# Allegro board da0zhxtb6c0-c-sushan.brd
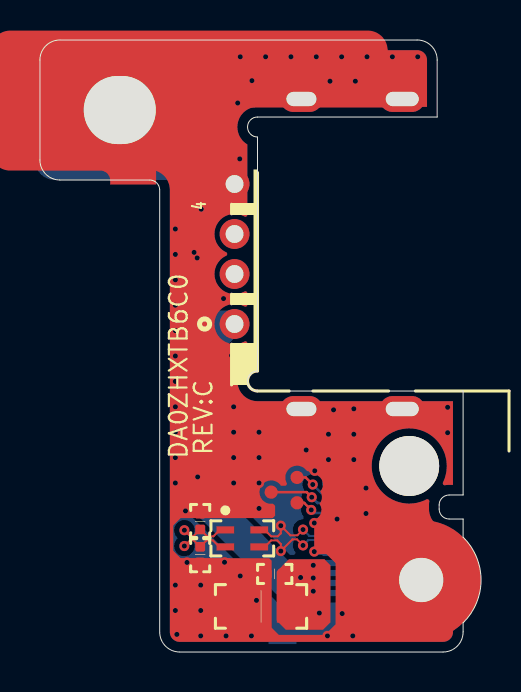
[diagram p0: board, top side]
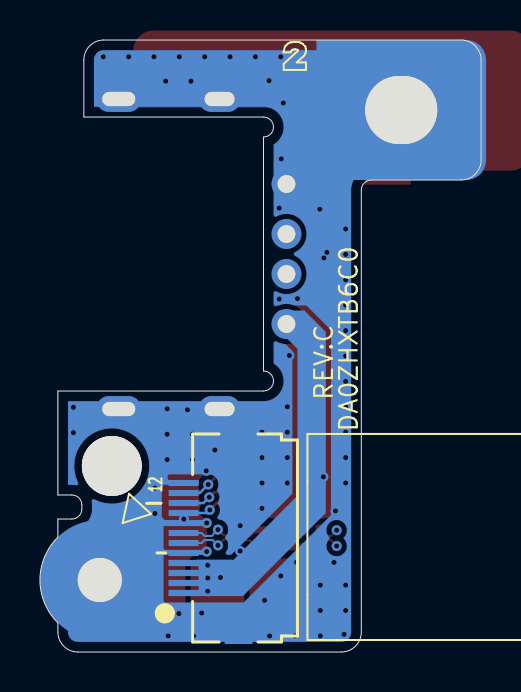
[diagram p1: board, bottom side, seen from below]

Outline 22.1 x 30.6 mm; copper layers: TOP, GND, IN1, IN2, VCC, BOTTOM. Coordinates in mm from the lower left corner of the outline.
Outline path: 0,29.6 0,24.6 arc(0.29,23.89) 1,23.6 5.5,23.6 arc(5.85,23.45) 6,23.1 6,1 arc(6.29,0.29) 7,0 20.2,0 arc(20.91,0.29) 21.2,1 21.2,1.46 arc(22.1,3.6) 21.2,5.74 21.2,6.65 20.5,6.65 arc(20.15,6.8) 20,7.15 20,7.35 arc(20.15,7.7) 20.5,7.85 21.2,7.85 21.2,13.05 10.9,13.05 arc(10.4,13.55) 10.9,14.05 10.9,25.75 arc(10.4,26.25) 10.9,26.75 19.9,26.75 19.9,29.6 arc(19.61,30.31) 18.9,30.6 1,30.6 arc(0.29,30.31) 0,29.6

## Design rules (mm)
constraint set DEFAULT: min track width 0.127

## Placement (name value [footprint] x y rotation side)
C1  100u/6.3v_1206  [C1206]  11.08 2.28 180 top
C2  0.1u/10v_4  [C0402]  11.76 3.9 0 top
CN1  ffc_conn  [AF712L-A2G1T-12P-L-SMT]  12.15 5.7 90 bottom
CN2  usb_con  [USB-C107V3-10406-L-4P-L]  18.15 19.9 90 top
D7  5v/30v/0.2p_4  [C0402]  8.03 6.52 270 top
D8  5v/30v/0.2p_4  [C0402]  8.03 4.87 90 top
HOLE1  *h-c118d118n  [H-C118D118N]  18.5 9.3 0 top
HOLE2  *h-c236d87p2  [H-C236D87P2]  19.1 3.6 0 top
HOLE3  *h-tc236bsdo142x134p2  [H-TC236BSDO142X134P2]  4 27.1 0 top
HOLE4  *spad-zhx-np  [SPAD-ZHX-NP]  7.47 27.22 0 top
L1  mcm2012b900gbe/400ma/90ohm  [CHOKE-DLW21S-4P]  10.14 5.68 0 top
NOREF  -  []  -27.94 -62.16 0 top
NOREF#2  -  []  22.86 -20 0 top
TP1  *pad  [TP2650]  12.88 7.46 0 top
TP2  *pad  [TP2650]  11.58 7.99 0 top
TP3  *pad  [TP2650]  12.88 8.73 0 top

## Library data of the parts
C1 = C1206
C2 D7 D8 = C0402
CN1 = AF712L-A2G1T-12P-L-SMT
CN2 = USB-C107V3-10406-L-4P-L
HOLE1 = H-C118D118N
HOLE2 = H-C236D87P2
HOLE3 = H-TC236BSDO142X134P2
HOLE4 = SPAD-ZHX-NP
L1 = CHOKE-DLW21S-4P
TP1-TP3 = TP2650

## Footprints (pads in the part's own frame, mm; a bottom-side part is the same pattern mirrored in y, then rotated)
AF712L-A2G1T-12P-L-SMT
  rect 0.305x1.499 smd: 1(-2.75,2.75) 2(-2.25,2.75) 3(-1.75,2.75) 4(-1.25,2.75) 5(-0.75,2.75) 6(-0.25,2.75) 7(0.25,2.75) 8(0.75,2.75) 9(1.25,2.75) 10(1.75,2.75) 11(2.25,2.75) 12(2.75,2.75)
  rect 1.803x1.397 smd: 13(-4.4,0) 14(4.4,0)
C0402
  custom 0.12x0.12 smd: 1(0.39,0) 2(-0.39,0)
C1206
  rect 1.219x1.626 smd: 1(1.4,0) 2(-1.4,0)
CHOKE-DLW21S-4P
  rect 0.889x0.356 smd: 1(-0.85,0.425) 2(0.85,0.425) 3(0.85,-0.425) 4(-0.85,-0.425)
H-C118D118N
  round 2.997 hole 2.997 unplated: (0,0)
H-C236D87P2
  round 5.994 hole 2.21: 1(0,0)
H-TC236BSDO142X134P2
  round 5.994 hole 3.607x3.404: 1(0,0)
SPAD-ZHX-NP
  custom 1.925x1.925 smd: 1(0,0)
TP2650
  round 0.66 smd: 1(0,0)
USB-C107V3-10406-L-4P-L
  round 1.499 hole 0.889: 1(-3.5,8.4) 2(-1,8.4) 3(1,8.4) 4(3.5,8.4)
  oval 1.295x2.108 hole 0.711x1.499: 5(-7.75,5.05) 6(7.75,5.05)
  oval 1.295x2.261 hole 0.711x1.651: 7(-7.75,0) 8(7.75,0)

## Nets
5VUSB_1: C1.2 C2.1 CN1.1 CN1.2 CN1.3 CN1.4 CN2.1
GND: C1.1 C2.2 CN1.5 CN1.8 CN1.12 CN1.13 CN1.14 CN2.4 CN2.5 CN2.6 CN2.7 CN2.8 D7.2 D8.2 HOLE2.1 HOLE3.1 HOLE4.1
NBSWON#: CN1.9 TP1.1
USBP1+: CN1.7 L1.2
USBP1+_CN: CN2.3 D7.1 L1.1
USBP1-: CN1.6 L1.3
USBP1-_CN: CN2.2 D8.1 L1.4
VOLUME_DOWN#: CN1.11 TP3.1
VOLUME_UP#: CN1.10 TP2.1

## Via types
v1: diameter 0.508, hole 0.254, TOP to BOTTOM, 85 vias

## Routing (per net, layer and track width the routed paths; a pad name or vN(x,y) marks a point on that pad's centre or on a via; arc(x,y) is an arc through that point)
5VUSB_1:
  vias: v1(13.06,3.73) v1(13.69,4.34) v1(13.69,3.7) v1(13.69,3.04) v1(14,1.95)
GND:
  vias: v1(6.78,21.15) v1(6.78,19.88) v1(6.78,18.61) v1(6.78,17.34) v1(6.78,16.07) v1(6.78,14.8) v1(6.78,13.53) v1(6.78,12.26) v1(6.78,10.99) v1(6.78,9.72) v1(6.78,8.45) v1(6.78,3.34) v1(6.78,2.07) v1(6.86,0.88) v1(7.29,7.05) v1(7.37,4.48) v1(7.72,19.98) v1(7.88,19.7) v1(7.9,8.75) v1(8.08,22.14) v1(8.05,3.34) v1(8.05,2.07) v1(8.05,0.8) v1(9.2,17.67) v1(9.25,4.49) v1(9.32,0.8) v1(9.6,14.83) v1(9.71,12.26) v1(9.71,10.99) v1(9.71,9.72) v1(9.71,8.45) v1(9.91,27.45) v1(10.04,29.76) v1(10.01,24.66) v1(10.04,3.8) v1(10.11,22.19) v1(10.11,17.64) v1(10.62,28.57) v1(10.59,0.8) v1(10.85,2.58) v1(10.98,10.99) v1(10.98,9.72) v1(10.98,8.45) v1(10.98,7.18) v1(11.31,29.76) v1(12.58,29.76) v1(13.34,10.1) v1(13.74,6.45) v1(13.74,5.02) v1(13.85,29.76) v1(13.77,9.06) v1(14.4,0.8) v1(14.53,28.54) v1(14.46,10.89) v1(14.46,9.62) v1(14.71,12.11) v1(14.89,6.65) v1(15.12,29.76) v1(15.14,1.92) v1(15.73,12.16) v1(15.73,10.89) v1(15.73,9.62) v1(15.67,0.8) v1(15.8,28.54) v1(16.33,8.2) v1(16.33,6.93) v1(16.39,29.76) v1(17.66,29.76) v1(18.93,29.76) v1(20.42,12.23) v1(20.42,10.96)
NBSWON#: length 2.2
  TOP w0.127: TP1.1 13.24,7.46 v1(13.59,7.1)
  BOTTOM w0.127: CN1.9 13.75,6.95 v1(13.59,7.1)
USBP1+: length 5
  TOP w0.102: v1(13.18,6.12) 12.89,5.83 12.55,5.83 v1(12.07,6.32) 12.07,5.94 11.92,5.78 11.58,5.78 11.26,6.11 L1.2
  BOTTOM w0.102: CN1.7 14,5.95 13.85,5.8 13.5,5.8 v1(13.18,6.12)
USBP1+_CN: length 20.5
  TOP w0.102: v1(7.24,6.09) 7.53,5.8 7.69,5.8 D7.1 8.38,5.78 8.69,5.78 9.01,6.11 L1.1
  IN1 w0.14: v1(7.24,6.09) 7.5,5.82 7.92,5.82 8.27,6.17 8.27,7.58 7.47,8.38 7.47,19.65 7.86,20.05 8.9,20.05 CN2.3
USBP1-: length 5
  TOP w0.102: L1.3 11.26,5.26 11.58,5.58 11.89,5.58 12.07,5.4 v1(12.07,5.05) 12.65,5.63 12.88,5.63 v1(13.18,5.33)
  BOTTOM w0.102: CN1.6 14,5.45 13.85,5.6 13.45,5.6 v1(13.18,5.33)
USBP1-_CN: length 20.5
  TOP w0.102: v1(7.24,5.3) 7.53,5.59 7.69,5.59 D8.1 8.35,5.58 8.66,5.58 8.99,5.26 L1.4
  IN1 w0.14: CN2.2 8.87,19.78 7.97,19.78 7.74,19.54 7.74,8.49 8.54,7.69 8.54,6.06 8.03,5.55 7.49,5.55 v1(7.24,5.3)
VOLUME_DOWN#: length 2.3
  TOP w0.127: v1(13.67,8.37) 13.31,8.73 TP3.1
  BOTTOM w0.127: v1(13.67,8.37) 14.09,7.95 CN1.11
VOLUME_UP#: length 3.5
  TOP w0.127: TP2.1 13.36,7.99 v1(13.62,7.74)
  BOTTOM w0.127: v1(13.62,7.74) 13.91,7.45 CN1.10

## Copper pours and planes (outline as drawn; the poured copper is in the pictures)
5VUSB_1 on TOP (solid shape): 14.56,4.34 14.56,1.49 14.18,1.11 12.32,1.11 11.86,1.57 11.86,4.03 12.47,4.64 14.25,4.64
5VUSB_1 on BOTTOM (solid shape): 10.37,16.83 10.37,16.32 9.2,15.16 9.2,7.82 12.41,4.6 15.65,4.6 15.65,4.3 14.15,4.3 14.15,4.1 15.65,4.1 15.65,3.8 14.15,3.8 14.15,3.6 15.65,3.6 15.65,3.3 14.15,3.3 14.15,3.1 15.65,3.1 15.65,2.8 11.93,2.8 7.77,6.95 7.77,15.99 8.85,17.07 10.12,17.07
5VUSB_1 on VCC (solid shape): 10.37,16.83 10.37,16.32 9.2,15.16 9.2,7.82 12.4,4.61 13.97,4.61 14.28,4.31 14.28,2.99 14,2.71 12.02,2.71 7.77,6.95 7.77,15.99 8.85,17.07 10.12,17.07
GND on TOP (solid shape): outline of 627 points within 0.51,0.51 21.59,30.09
GND on BOTTOM (solid shape): outline of 654 points within 0.51,0.51 21.59,30.09
GND on GND (solid shape): outline of 834 points within 0.51,0.51 21.59,30.09
GND on IN1 (solid shape): outline of 800 points within 0.51,0.51 21.59,30.09
GND on IN2 (solid shape): outline of 831 points within 0.51,0.51 21.59,30.09
GND on VCC (solid shape): outline of 706 points within 0.51,0.51 21.59,30.09

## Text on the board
Ref Des/Silkscreen Bottom: DA0ZHXTB6C0 | REV:C
Ref Des/Silkscreen Top: DA0ZHXTB6C0 | REV:C
GND: GND | 2
VCC: VCC | 5
User.45: FIGURE | TYPE | Oblong | Circle | SIZE | 59.0x28.0 | 65.0x28.0 | 142.0x134.0 | 10.0 | 35.0 | 87.0 | 118.0 | DRILL CHART: TOP to BOTTOM | ALL UNITS ARE IN MILS | PLATED | NON-PLATED | ROTATION | 0.000 | - | QTY | 2 | 1 | 5 | 76 | 4 | 82 | TOTAL HOLES:
